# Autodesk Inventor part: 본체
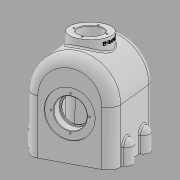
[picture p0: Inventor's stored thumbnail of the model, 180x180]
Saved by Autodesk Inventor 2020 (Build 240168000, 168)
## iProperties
Created: 2023-03
Part Number: 본체
Material: 일반
Document SubType Name: Modeling
Designer: user
Density: 1 g/cm^3
Appearance: 기본값
Author: user
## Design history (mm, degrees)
sketch "스케치1"
  geometry: L1 (-70, -94)-(70, -94); L2 (70, -94)-(70, 0); L3 (70, 0)-(-70, 0); L4 (-70, 0)-(-70, -94); 2 further points
  constraints: 8 end point, 2 parallel, 1 coincident, 1 horizontal, 1 midpoint, 1 perpendicular
  dimensions: "d0" = 140 distance of L3.end L2.end; "d1" = 94 distance of L2.end L1.end
extrude "돌출1" new body sketch "스케치1" stored distance "d2" = 130; taper "d3" = 0 deg
sketch "스케치2"
  geometry: L1 (70, 0)-(-70, 0) reference; A1 r 70 centre (0, 0) between (70, 0) and (-70, 0); 1 further point
  constraints: 2 point on circle, 1 centre point, 1 coincident
extrude "돌출2" join sketch "스케치2" distance "d5" = 130; taper "d6" = 0 deg
node "작업 평면1"
feature "쉘1" dims "d11" = 10
node "작업 평면2"
sketch "스케치7"
  geometry: L1 (60, -94)-(-60, -94) reference; L2 (0, -94)-(0, -19); C1 r 40 at (0, -19)
  constraints: 2 end point, 1 centre point, 1 coincident, 1 midpoint, 1 vertical
  dimensions: "d35" = 75 distance of L2.start L2.end; "d36" = 80 diameter of C1
extrude "돌출4" cut sketch "스케치7" distance "d37" = 2; taper "d38" = 0 deg
node "작업 평면3"
node "작업 평면4"
sketch "스케치13"
  geometry: L1 (60, -94)-(-60, -94) reference; L2 (0, -94)-(0, -19); C1 r 40 at (0, -19) reference; C2 r 30 at (0, -19); 1 further point
  constraints: 2 end point, 1 centre point, 1 coincident, 1 midpoint, 1 vertical
  dimensions: "d73" = 75 distance of L2.start L2.end; "d74" = 60 diameter of C2
extrude "돌출7" join sketch "스케치13" distance "d75" = 12; taper "d76" = 45 deg
sketch "스케치14"
  geometry: C1 r 40 at (0, 0) reference; 2 further points
  constraints: 1 coincident
hole "구멍6" sketch "스케치14" at (0, 0) diameter "d77" = 46; stored, may be unused: countersink angle "d81" = 90 deg, drill point angle "d83" = 118 deg; dims "d78" = 8, "d79" = 52, "d80" = 18, "d82" = 10
sketch "스케치15"
  geometry: L1 (0, 0)-(0, 30); C1 r 40 at (0, 0) reference; 2 further points
  constraints: 2 end point, 1 coincident, 1 vertical
  dimensions: "d84" = 30 distance of L1.start L1.end
hole "구멍7" sketch "스케치15" at (0, 30) diameter "d85" = 3.242; stored, may be unused: countersink angle "d89" = 90 deg, drill point angle "d91" = 118 deg; dims "d86" = 8, "d87" = 52, "d88" = 18, "d90" = 10
chamfer "모따기1" distance "d95" = 1; stored, may be unused: second distance "d96" = 2, angle "d97" = 45 deg
fillet "모깎기1" dims "d98" = 20
sketch "스케치16"
  geometry: L1 (120, 20)-(120, 110) reference; L2 (120, 104)-(120, 80); A1 r 12 centre (120, 92) between (120, 80) and (120, 104); 1 further point
  constraints: 3 point on line, 2 end point, 2 point on circle, 1 centre point, 1 collinear
  dimensions: "d100" = 24 diameter of A1; "d101" = 27 vertical distance of point (50, 65) A1.centre
extrude "돌출8" join sketch "스케치16" distance "d102" = 28; taper "d103" = 0 deg
node "작업 평면5"
sketch "스케치18"
  geometry: L1 (82, -66)-(70, -66) reference; L2 (70, -54)-(70, -66); L3 (70, 0)-(70, -94) reference; L4 (70, -66)-(82, -66); A1 r 12 centre (70, -66) between (82, -66) and (70, -54); 1 further point
  constraints: 4 end point, 2 point on circle, 1 centre point, 1 collinear, 1 perpendicular
revolve "회전1" sketch "스케치18" stored, may be unused: angle "d112" = 180 deg
sketch "스케치19"
  geometry: A1 r 12 centre (120, 92) between (120, 80) and (120, 104) reference; 2 further points
  constraints: 1 coincident
hole "구멍9" sketch "스케치19" at (120, 92) diameter "d113" = 10.106; stored, may be unused: countersink angle "d117" = 90 deg, drill point angle "d119" = 118 deg; dims "d114" = 24, "d115" = 52, "d116" = 18, "d118" = 26
fillet "모깎기3" dims "d120" = 3
fillet "모깎기4" dims "d121" = 10
fillet "모깎기5" dims "d122" = 1
fillet "모깎기6" dims "d123" = 3
fillet "모깎기7" dims "d124" = 3
node "작업 평면6"
sketch "스케치20"
  geometry: C1 r 35 at (-50, -65); 1 further point
  constraints: 1 centre point, 1 coincident
  dimensions: "d126" = 70 diameter of C1
extrude "돌출9" join sketch "스케치20" stored distance "d127" = 28; taper "d128" = 0 deg
sketch "스케치21"
  geometry: C1 r 35 at (0, 0) reference; 1 further point
  constraints: 1 coincident
hole "구멍10" sketch "스케치21" at (0, 0) diameter "d129" = 34; stored, may be unused: countersink angle "d133" = 90 deg, drill point angle "d135" = 118 deg; dims "d130" = 24, "d131" = 43, "d132" = 22, "d134" = 26
sketch "스케치22"
  geometry: L1 (0, 0)-(-26, 0); C1 r 35 at (0, 0) reference; 1 further point
  constraints: 2 end point, 1 coincident, 1 horizontal
  dimensions: "d136" = 26 distance of L1.start L1.end
hole "구멍11" sketch "스케치22" at (-26, 0) diameter "d137" = 3.242; stored, may be unused: countersink angle "d141" = 90 deg, drill point angle "d143" = 118 deg; dims "d138" = 8, "d139" = 43, "d140" = 22, "d142" = 10
chamfer "모따기2" distance "d147" = 1; stored, may be unused: second distance "d148" = 2, angle "d149" = 45 deg
fillet "모깎기8" dims "d150" = 3
node "작업 평면7"
sketch "스케치23"
  geometry: L1 (84, -35)-(84, 35) reference; 2 further points
  constraints: 1 horizontal alignment, 1 other
  dimensions: "d153" = 8 distance from line of L1 point (76, 0)
feature "엠보싱2" sketch "스케치23" dims "d35" = 75, "d36" = 80, "d154" = 0.5, "d155" = 0
node "솔리드1"
mirror "미러5"
pattern_circular "원형 패턴3" dims angle "d93" = 360 deg
mirror "미러6"
mirror "미러7"
mirror "미러8"
mirror "미러9"
pattern_circular "원형 패턴4" dims angle "d145" = 360 deg
feature "A9D066F2-1C7D-4E18-AEED-F7BC21143FA4" dims "d77" = 46, "d78" = 8, "d79" = 52, "d80" = 18, "d81" = 90 deg, "d82" = 10, "d83" = 118 deg
other parameters: "d7" = -178, "d68" = -22, "d72" = -22, "d111" = 27, "d125" = -178
